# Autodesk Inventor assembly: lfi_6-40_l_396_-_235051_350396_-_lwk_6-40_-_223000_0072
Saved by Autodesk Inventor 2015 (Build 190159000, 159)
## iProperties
Created: 2022-03
Part Number: lfi_6-40_l_396_-_235051_350396_-_lwk_6-40_-_223000_0072
Checked By: TraceParts S.A.
Catalog Web Link: www.traceparts.com
Document SubType Name: Assembly
Designer: TraceParts
Company: TraceParts S.A.
Author: TraceParts
REFERENCE: LFI 6-40 L=396 - 235051 350396 - LWK 6-40 - 223000 0072
SUPPLIER: isel Germany AG
DESIGN: Linearführungsschiene LFI-6-40
TraceParts.PartNumber: 30-08032016-071819
TraceParts.PartTitle: Linearführungsschiene LFI-6-40
TraceParts.InstanceId: 30-08032016-071819ESEO346ZL4G6LL4W8HRU5J6IO
TraceParts.PartVersion: 1.0.4
TraceParts.PartLanguage: de
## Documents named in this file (31)
- C:\TPO v2\SharedFS\Outgoing\lfi_6-40_l_396_-_235051_350396_-_lwk_6-40_-_223000_0072.iam
- C:\TPO v2\SharedFS\Outgoing\lfi_6-40_l_396_-_235051_350396_-_lwk_6-40_-_223000_0072_01.ipt
- C:\TPO v2\SharedFS\Outgoing\lfi_6-40_l_396_-_235051_350396_-_lwk_6-40_-_223000_0072_02.ipt
- C:\TPO v2\SharedFS\Outgoing\lfi_6-40_l_396_-_235051_350396_-_lwk_6-40_-_223000_0072_03.ipt
- C:\TPO v2\SharedFS\Outgoing\lfi_6-40_l_396_-_235051_350396_-_lwk_6-40_-_223000_0072_04.ipt
- C:\TPO v2\SharedFS\Outgoing\lfi_6-40_l_396_-_235051_350396_-_lwk_6-40_-_223000_0072_05.ipt
- C:\TPO v2\SharedFS\Outgoing\lfi_6-40_l_396_-_235051_350396_-_lwk_6-40_-_223000_0072_06.ipt
- C:\TPO v2\SharedFS\Outgoing\lfi_6-40_l_396_-_235051_350396_-_lwk_6-40_-_223000_0072_07.ipt
- C:\TPO v2\SharedFS\Outgoing\lfi_6-40_l_396_-_235051_350396_-_lwk_6-40_-_223000_0072_08.ipt
- C:\TPO v2\SharedFS\Outgoing\lfi_6-40_l_396_-_235051_350396_-_lwk_6-40_-_223000_0072_09.ipt
- C:\TPO v2\SharedFS\Outgoing\lfi_6-40_l_396_-_235051_350396_-_lwk_6-40_-_223000_0072_10.ipt
- C:\TPO v2\SharedFS\Outgoing\lfi_6-40_l_396_-_235051_350396_-_lwk_6-40_-_223000_0072_11.ipt
- C:\TPO v2\SharedFS\Outgoing\lfi_6-40_l_396_-_235051_350396_-_lwk_6-40_-_223000_0072_12.ipt
- C:\TPO v2\SharedFS\Outgoing\lfi_6-40_l_396_-_235051_350396_-_lwk_6-40_-_223000_0072_13.ipt
- C:\TPO v2\SharedFS\Outgoing\lfi_6-40_l_396_-_235051_350396_-_lwk_6-40_-_223000_0072_14.ipt
- C:\TPO v2\SharedFS\Outgoing\lfi_6-40_l_396_-_235051_350396_-_lwk_6-40_-_223000_0072_15.ipt
- C:\TPO v2\SharedFS\Outgoing\lfi_6-40_l_396_-_235051_350396_-_lwk_6-40_-_223000_0072_16.ipt
- C:\TPO v2\SharedFS\Outgoing\lfi_6-40_l_396_-_235051_350396_-_lwk_6-40_-_223000_0072_17.ipt
- C:\TPO v2\SharedFS\Outgoing\lfi_6-40_l_396_-_235051_350396_-_lwk_6-40_-_223000_0072_18.ipt
- C:\TPO v2\SharedFS\Outgoing\lfi_6-40_l_396_-_235051_350396_-_lwk_6-40_-_223000_0072_19.ipt
- C:\TPO v2\SharedFS\Outgoing\lfi_6-40_l_396_-_235051_350396_-_lwk_6-40_-_223000_0072_20.ipt
- C:\TPO v2\SharedFS\Outgoing\lfi_6-40_l_396_-_235051_350396_-_lwk_6-40_-_223000_0072_21.ipt
- C:\TPO v2\SharedFS\Outgoing\lfi_6-40_l_396_-_235051_350396_-_lwk_6-40_-_223000_0072_22.ipt
- C:\TPO v2\SharedFS\Outgoing\lfi_6-40_l_396_-_235051_350396_-_lwk_6-40_-_223000_0072_23.ipt
- C:\TPO v2\SharedFS\Outgoing\lfi_6-40_l_396_-_235051_350396_-_lwk_6-40_-_223000_0072_24.ipt
- C:\TPO v2\SharedFS\Outgoing\lfi_6-40_l_396_-_235051_350396_-_lwk_6-40_-_223000_0072_25.ipt
- C:\TPO v2\SharedFS\Outgoing\lfi_6-40_l_396_-_235051_350396_-_lwk_6-40_-_223000_0072_26.ipt
- C:\TPO v2\SharedFS\Outgoing\lfi_6-40_l_396_-_235051_350396_-_lwk_6-40_-_223000_0072_27.ipt
- C:\TPO v2\SharedFS\Outgoing\lfi_6-40_l_396_-_235051_350396_-_lwk_6-40_-_223000_0072_28.ipt
- C:\TPO v2\SharedFS\Outgoing\lfi_6-40_l_396_-_235051_350396_-_lwk_6-40_-_223000_0072_29.ipt
- C:\TPO v2\SharedFS\Outgoing\lfi_6-40_l_396_-_235051_350396_-_lwk_6-40_-_223000_0072_30.ipt
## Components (30 placed, 30 different names)
1. lfi_6-40_l_396_-_235051_350396_-_lwk_6-40_-_223000_0072_01:1
2. lfi_6-40_l_396_-_235051_350396_-_lwk_6-40_-_223000_0072_02:1
3. lfi_6-40_l_396_-_235051_350396_-_lwk_6-40_-_223000_0072_03:1
4. lfi_6-40_l_396_-_235051_350396_-_lwk_6-40_-_223000_0072_04:1
5. lfi_6-40_l_396_-_235051_350396_-_lwk_6-40_-_223000_0072_05:1
6. lfi_6-40_l_396_-_235051_350396_-_lwk_6-40_-_223000_0072_06:1
7. lfi_6-40_l_396_-_235051_350396_-_lwk_6-40_-_223000_0072_07:1
8. lfi_6-40_l_396_-_235051_350396_-_lwk_6-40_-_223000_0072_08:1
9. lfi_6-40_l_396_-_235051_350396_-_lwk_6-40_-_223000_0072_09:1
10. lfi_6-40_l_396_-_235051_350396_-_lwk_6-40_-_223000_0072_10:1
11. lfi_6-40_l_396_-_235051_350396_-_lwk_6-40_-_223000_0072_11:1
12. lfi_6-40_l_396_-_235051_350396_-_lwk_6-40_-_223000_0072_12:1
13. lfi_6-40_l_396_-_235051_350396_-_lwk_6-40_-_223000_0072_13:1
14. lfi_6-40_l_396_-_235051_350396_-_lwk_6-40_-_223000_0072_14:1
15. lfi_6-40_l_396_-_235051_350396_-_lwk_6-40_-_223000_0072_15:1
16. lfi_6-40_l_396_-_235051_350396_-_lwk_6-40_-_223000_0072_16:1
17. lfi_6-40_l_396_-_235051_350396_-_lwk_6-40_-_223000_0072_17:1
18. lfi_6-40_l_396_-_235051_350396_-_lwk_6-40_-_223000_0072_18:1
19. lfi_6-40_l_396_-_235051_350396_-_lwk_6-40_-_223000_0072_19:1
20. lfi_6-40_l_396_-_235051_350396_-_lwk_6-40_-_223000_0072_20:1
21. lfi_6-40_l_396_-_235051_350396_-_lwk_6-40_-_223000_0072_21:1
22. lfi_6-40_l_396_-_235051_350396_-_lwk_6-40_-_223000_0072_22:1
23. lfi_6-40_l_396_-_235051_350396_-_lwk_6-40_-_223000_0072_23:1
24. lfi_6-40_l_396_-_235051_350396_-_lwk_6-40_-_223000_0072_24:1
25. lfi_6-40_l_396_-_235051_350396_-_lwk_6-40_-_223000_0072_25:1
26. lfi_6-40_l_396_-_235051_350396_-_lwk_6-40_-_223000_0072_26:1
27. lfi_6-40_l_396_-_235051_350396_-_lwk_6-40_-_223000_0072_27:1
28. lfi_6-40_l_396_-_235051_350396_-_lwk_6-40_-_223000_0072_28:1
29. lfi_6-40_l_396_-_235051_350396_-_lwk_6-40_-_223000_0072_29:1
30. lfi_6-40_l_396_-_235051_350396_-_lwk_6-40_-_223000_0072_30:1
